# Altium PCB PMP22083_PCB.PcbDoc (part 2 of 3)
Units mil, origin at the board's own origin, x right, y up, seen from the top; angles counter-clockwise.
Board outline 6200 x 4200 mil, 2 copper layers (Top Layer, Bottom Layer), stack 62 mil thick; 186 components, 87 nets, 426 pads, 96 vias.
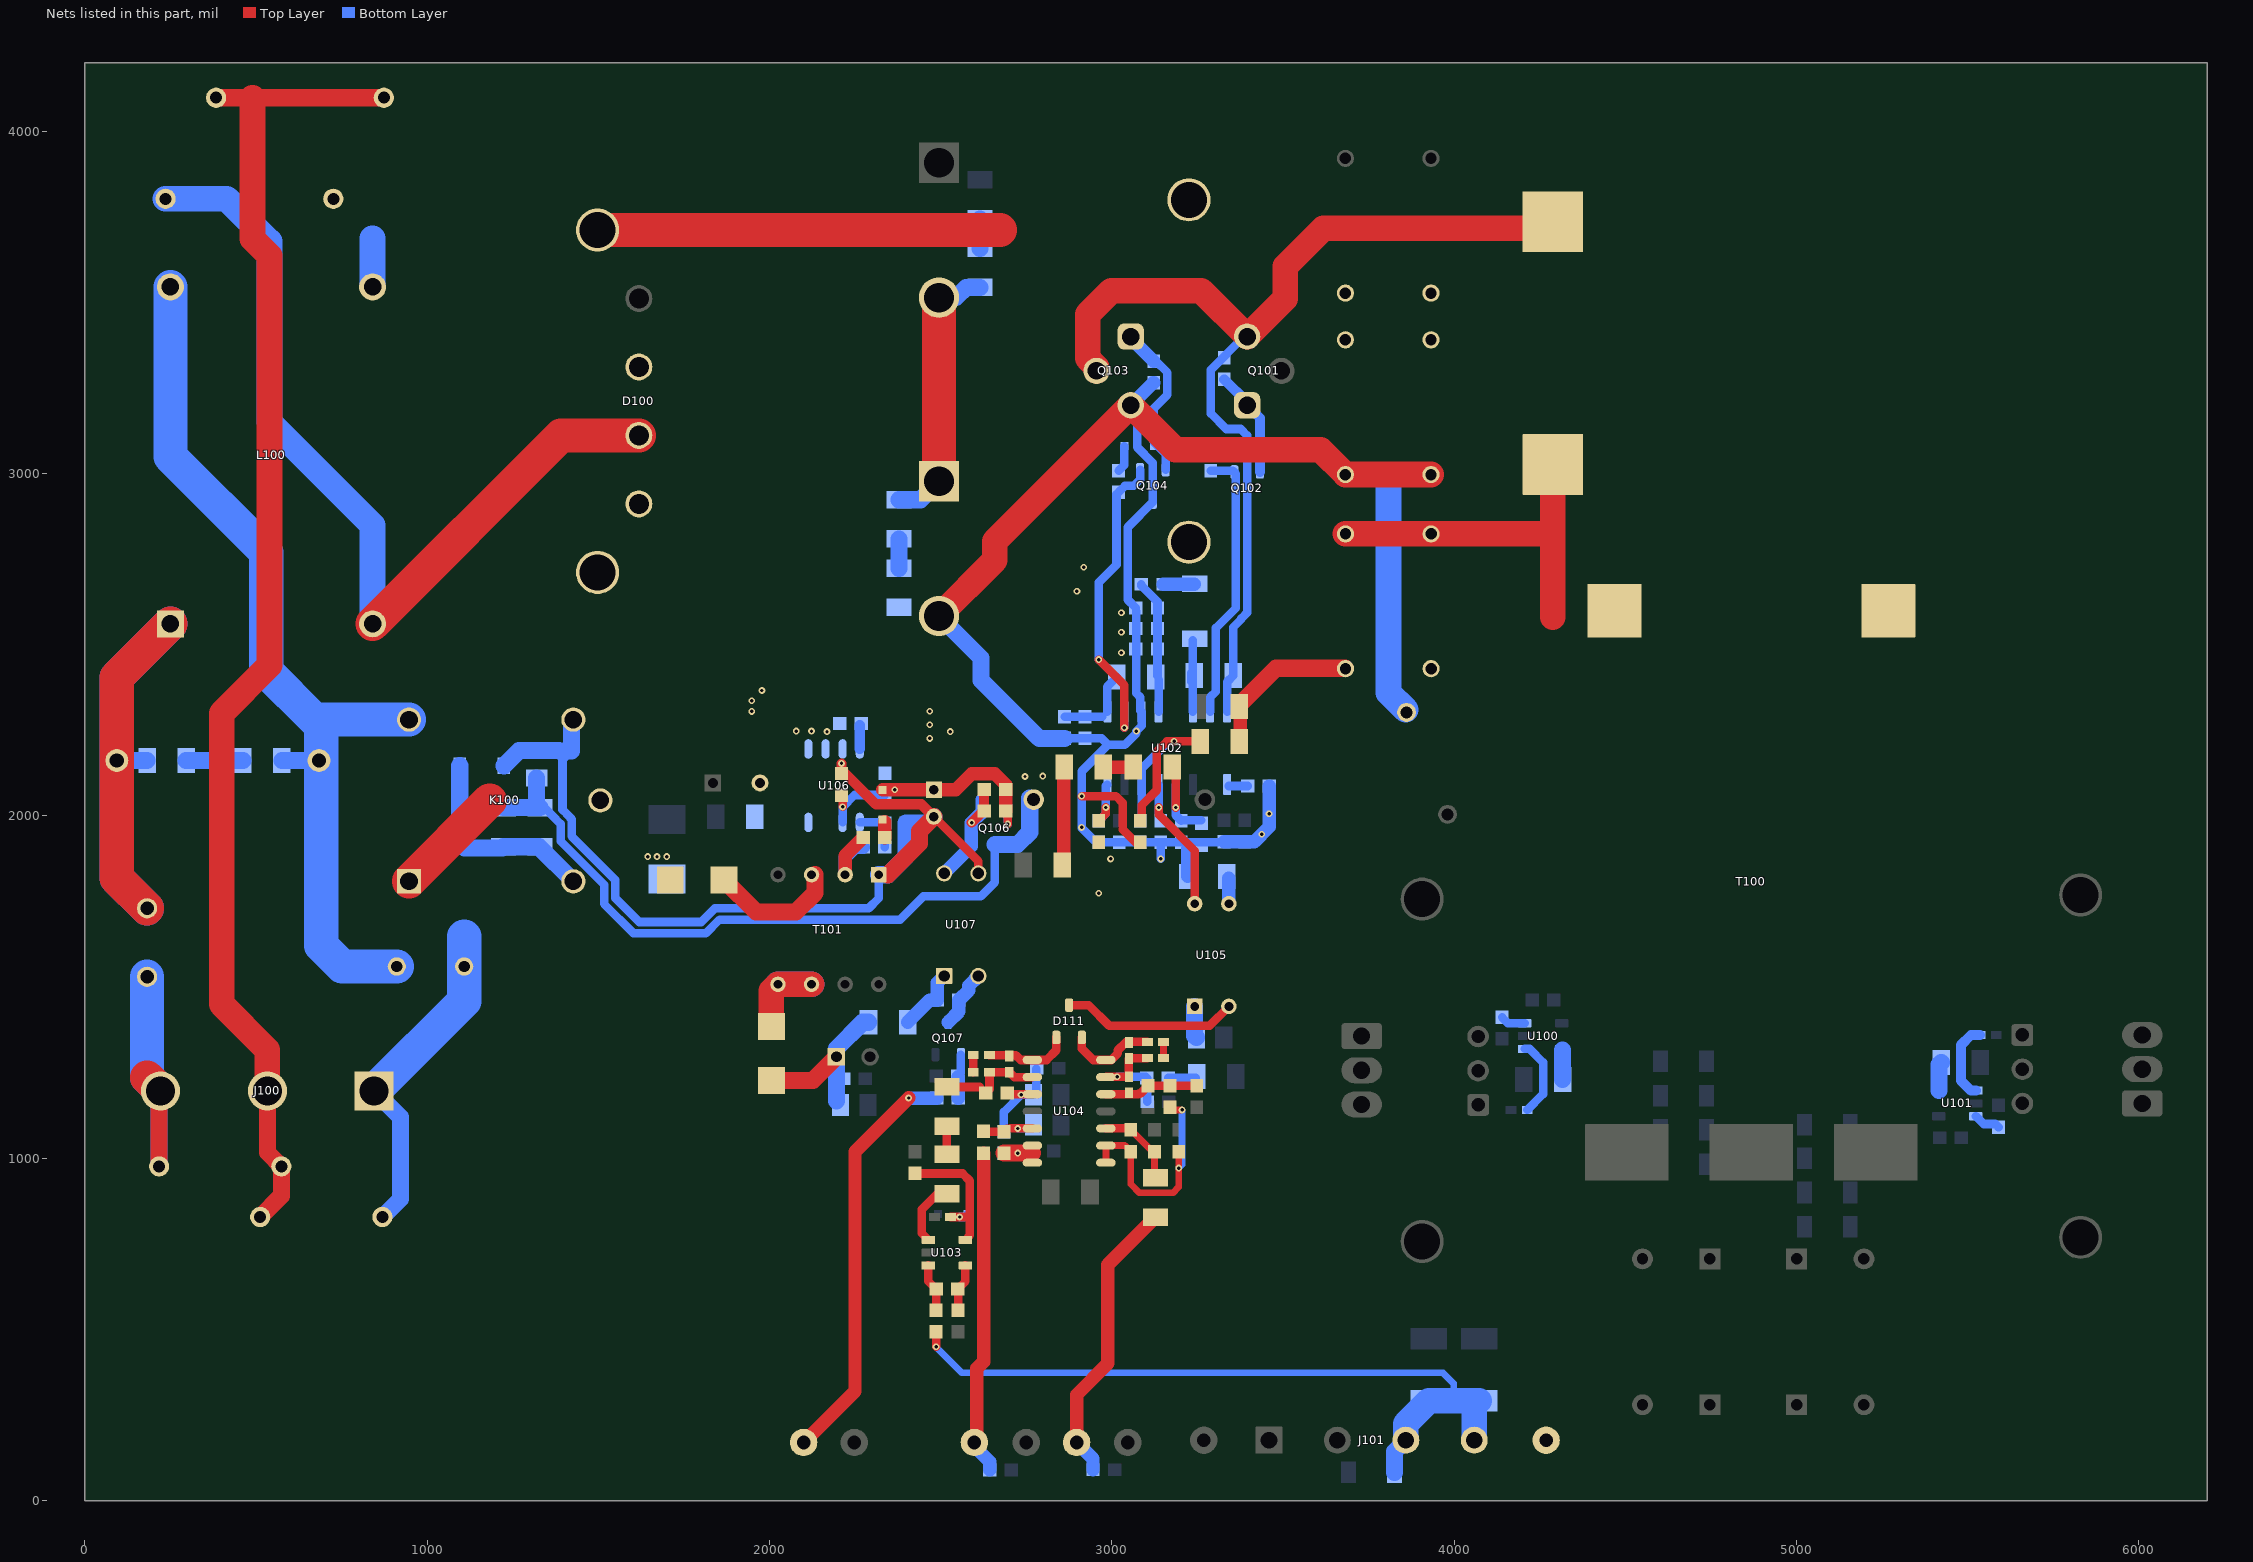
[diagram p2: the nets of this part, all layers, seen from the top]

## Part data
C100 C108: library part CMP-0010098-2, "CAP, AL, 560 uF, 200 V, +/- 20%, TH", Manufacturer=Nichicon, PartNumber=LGR2D561MELZ45, Tolerance_%=20%, Value1=Unknown, Value2=200V, ValueDisplayed=560uF
C101 C103: "CAP, CERM, 2.2 £gF, 16 V,+/- 20%, X5R, 0603", Cap_Case=0603, Manufacturer="Wurth Elektronik", Supplier Part Number 1=732-7915-1-ND, TempCo=X5R, Tolerance_%=20, Value2=16V, ValueDisplayed=2.2£gF
C102 C104: "CAP, CERM, 0.1 £gF, 50 V,+/- 10%, X7R, 0603", Cap_Case=0603, Manufacturer="Wurth Elektronik", TempCo=X7R, Tolerance_%=10, Value2=50V, ValueDisplayed=0.1£gF
C105 C106 C110 C111: "CAP, CERM, 470pF, 300V, +/-10%, VY2, 5x7.5 mm", Cap_Case="Disk, 5x7.5 mm", Manufacturer=Vishay-Bccomponents, Supplier Part Number 1=BC2352-ND, TempCo=VY2, Tolerance_%=10, Value1=Unknown, Value2=300V, ValueDisplayed=470pF
C107: "CAP, Film, 0.33uF, 275V, +/-20%, TH", Cap_Case=Radial,17.5x17.5x9.5mm, Manufacturer=Panasonic, Supplier Part Number 1=P10733-ND, Tolerance_%=20, Value1=Unknown, Value2=275V, ValueDisplayed=0.33£gF
C109: "CAP, CERM, 2200 pF, 300 V, +/- 20%, Y5U, AEC-Q200 Grade 1, D9.5xT5mm", Cap_Case=9.5x5mm, Manufacturer=Vishay-Bccomponents, Supplier Part Number 1=BC2914-ND, TempCo=Y5U, Tolerance_%=20, Value1=Unknown, Value2=300V, ValueDisplayed=2200pF
C112 C113 C114 C115 C116 C117: library part CMP-0074802-2, "CAP FILM 10000PF 5% 1KVDC RADIAL", Cap_Case=13x6x12mm, Manufacturer=TDK, Tolerance_%=5%, Value2=1000V, ValueDisplayed=0.01£gF
C118: "CAP, CERM, 22 pF, 1000 V,+/- 5%, C0G/NP0, 1206", Cap_Case=1206, Manufacturer=Vishay-Vitramon, Supplier Part Number 1=720-1013-1-ND, TempCo=C0G/NP0, Tolerance_%=5, Value2=1kV, ValueDisplayed=22pF
C119: "CAP, CERM, 150 pF, 630 V, +/- 5%, C0G/NP0, 1206", Cap_Case=1206, Manufacturer=MuRata, Supplier Part Number 1=490-5274-1-ND, TempCo=C0G/NP0, Tolerance_%=5, Value1=Unknown, Value2=630V, ValueDisplayed=150pF
C120 C121 C122 C123 C128 C165 C166 C167 C168: "CAP, CERM, 4.7 £gF, 50 V,+/- 10%, X7R, 1206", Cap_Case=1206, Manufacturer="Taiyo Yuden", Supplier Part Number 1=587-2994-2-ND, TempCo=X7R, Tolerance_%=10, Value2=50V, ValueDisplayed=4.7£gF
C124 C125 C126 C127: library part EEU-FR1V681, "CAP ALUM POLY 470UF 20% 25V T/H", Manufacturer=Panasonic, Tolerance_%=20, Value2=25V, ValueDisplayed=470£gF
C129: "CAP, CERM, 1uF, 16V, +/-10%, X5R, 0805", Cap_Case=0805, Manufacturer=AVX, Supplier Part Number 1=478-1411-1-ND, TempCo=X5R, Tolerance_%=10, Value1="0.012 ohm", Value2=16V, ValueDisplayed=1£gF
C130: "CAP, CERM, 2.2 £gF, 16 V, +/- 10%, X7R, 1206", Cap_Case=1206, Manufacturer=Kemet, Supplier Part Number 1=80-C1206C225K4R, TempCo=X7R, Tolerance_%=10, Value1="0.009 ohm", Value2=16V, ValueDisplayed=2.2£gF
C131: "CAP, CERM, 47 pF, 50 V, +/- 5%, C0G/NP0, 0603", Cap_Case=0603, Manufacturer=Kemet, Supplier Part Number 1=399-1056-1-ND, TempCo=C0G/NP0, Tolerance_%=5, Value1=Unknown, Value2=50V, ValueDisplayed=47pF
C132: "CAP, CERM, 0.1 £gF, 25 V, +/- 10%, X5R, 0402", Cap_Case=0402, Manufacturer=MuRata, Supplier Part Number 1=81-GRM155R61E104KA7D, TempCo=X5R, Tolerance_%=10, Value1=Unknown, Value2=25V, ValueDisplayed=0.1£gF
C133: "CAP, CERM, 0.1 £gF, 50 V, +/- 10%, X7R, 1206", Cap_Case=1206, Manufacturer=Kemet, Supplier Part Number 1=399-1249-1-ND, TempCo=X7R, Tolerance_%=10, Value1="0.059 ohm", Value2=50V, ValueDisplayed=0.1£gF
C134 C135 C139 C140 C141: "CAP, CERM, 4.7 £gF, 16 V, +/- 10%, X5R, 0603", Cap_Case=0603, Manufacturer=MuRata, Supplier Part Number 1=490-10481-1-ND, TempCo=X5R, Tolerance_%=10, Value1=Unknown, Value2=16V, ValueDisplayed=4.7£gF
C136 C155: "CAP, CERM, 0.01 £gF, 50 V, +/- 10%, X7R, 0402", Cap_Case=0402, Manufacturer=MuRata, Supplier Part Number 1=490-4516-1-ND, TempCo=X7R, Tolerance_%=10, Value1=Unknown, Value2=50V, ValueDisplayed=0.01£gF
C137: "CAP, CERM, 0.033 £gF, 16 V,+/- 10%, X5R, 0402", Cap_Case=0402, Manufacturer=MuRata, Supplier Part Number 1=490-5416-1-ND, TempCo=X5R, Tolerance_%=10, Value2=16V, ValueDisplayed=0.033£gF
C138: "CAP, CERM, 22 pF, 50 V,+/- 5%, C0G/NP0, 0603", Cap_Case=0603, Manufacturer=AVX, Supplier Part Number 1=478-1167-1-ND, TempCo=C0G/NP0, Tolerance_%=5, Value1="0.259 ohm", Value2=50V, ValueDisplayed=22pF
C142: "CAP, CERM, 0.47 £gF, 10 V,+80/-20%, Y5V, 0603", Cap_Case=0603, Manufacturer=Kemet, Supplier Part Number 1=399-3218-1-ND, TempCo=Y5V, Tolerance_%=80, Value2=10V, ValueDisplayed=0.47£gF
C143: "CAP, CERM, 2700 pF, 25 V,+/- 10%, X7R, 0603", Cap_Case=0603, Manufacturer=MuRata, Supplier Part Number 1=GRM188R71E272KA01D-ND, TempCo=X7R, Tolerance_%=10, Value2=25V, ValueDisplayed=2700pF
C144: "CAP, CERM, 47 pF, 50 V, +/- 1%, C0G/NP0, 0603", Cap_Case=0603, Manufacturer=MuRata, Supplier Part Number 1=490-9687-1-ND, TempCo=C0G/NP0, Tolerance_%=1, Value1=Unknown, Value2=50V, ValueDisplayed=47pF
C145: "CAP, CERM, 220 pF, 50 V, +/- 10%, X7R, 0603", Cap_Case=0603, Manufacturer=MuRata, Supplier Part Number 1=490-1483-1-ND, TempCo=X7R, Tolerance_%=10, Value1=Unknown, Value2=50V, ValueDisplayed=220pF
C146: "CAP, CERM, 2.2 pF, 50 V, +/- 11%, C0G/NP0, 0603", Cap_Case=0603, Manufacturer=AVX, Supplier Part Number 1=478-1155-1-ND, TempCo=C0G/NP0, Tolerance_%=11, Value1="1.033 ohm", Value2=50V, ValueDisplayed=2.2pF
C147 C148 C160: "CAP, CERM, 47 pF, 50 V,+/- 5%, C0G/NP0, 0603", Cap_Case=0603, Manufacturer=MuRata, Supplier Part Number 1=490-1419-1-ND, TempCo=C0G/NP0, Tolerance_%=5, Value2=50V, ValueDisplayed=47pF
C149 C150: "CAP, CERM, 0.1 £gF, 25 V,+/- 5%, X7R, 0805", Cap_Case=0805, Manufacturer=AVX, Supplier Part Number 1=478-7946-1-ND, TempCo=X7R, Tolerance_%=5, Value2=25V, ValueDisplayed=0.1£gF
C151: "CAP, AL, 2.2 £gF, 450 V, +/- 20%, 150.71 ohm, TH", Cap_Case=8x11.5mm, Manufacturer="Illinois Capacitor", Supplier Part Number 1=225CKE450MJM-ND, Tolerance_%=20, Value1="150.71 ohm", Value2=450V, ValueDisplayed=2.2£gF
C152: "CAP, CERM, 0.01 £gF, 250 V,+/- 10%, X7R, 1206", Cap_Case=1206, Manufacturer=Kemet, Supplier Part Number 1=399-4671-1-ND, TempCo=X7R, Tolerance_%=10, Value2=250V, ValueDisplayed=0.01£gF
C153: "CAP, AL, 100 £gF, 25 V, +/- 20%, TH", Cap_Case=6.3x11.2mm, Manufacturer=Panasonic, Supplier Part Number 1=P5540-ND, Tolerance_%=20, Value2=25V, ValueDisplayed=100£gF
C154: "CAP, CERM, 0.1uF, 25V, +/-10%, X7R, 0805", Cap_Case=0805, Manufacturer=AVX, Supplier Part Number 1=478-3755-1-ND, TempCo=X7R, Tolerance_%=10, Value1="0.28 ohm", Value2=25V, ValueDisplayed=0.1u
C156: "CAP, CERM, 0.022 £gF, 50 V,+/- 10%, C0G/NP0, 0402", Cap_Case=0402, Manufacturer=MuRata, Supplier Part Number 1=490-4763-1-ND, TempCo=C0G/NP0, Tolerance_%=10, Value2=50V, ValueDisplayed=0.022£gF
C157: "CAP, CERM, 0.01 £gF, 16 V,+/- 10%, X7R, 0603", Cap_Case=0603, Manufacturer="Wurth Elektronik", Supplier Part Number 1=732-7959-1-ND, TempCo=X7R, Tolerance_%=10, Value2=16V, ValueDisplayed=0.01£gF
C158: "CAP, CERM, 0.1uF, 50V, +/-10%, X7R, 0603", Cap_Case=0603, Manufacturer=AVX, Supplier Part Number 1=478-5052-1-ND, TempCo=X7R, Tolerance_%=10, Value1=Unknown, Value2=50V, ValueDisplayed=0.1u
C159: "CAP, CERM, 47 pF, 50 V,+/- 5%, C0G/NP0, 0402", Cap_Case=0402, Manufacturer=MuRata, Supplier Part Number 1=81-GRM1555C1H470JA1D, TempCo=C0G/NP0, Tolerance_%=5, Value2=50V, ValueDisplayed=47pF
C161 C162: "CAP, CERM, 0.1 £gF, 50 V,+/- 10%, X7R, 0603", Cap_Case=0603, Manufacturer=AVX, Supplier Part Number 1=478-5052-1-ND, TempCo=X7R, Tolerance_%=10, Value2=50V, ValueDisplayed=0.1£gF
C163: library part 25ML22MEFC5X5, "CAP, AL, 18uF, 35V, +/-20%, TH", Cap_Case=5x5, Manufacturer=Rubycon, Tolerance_%=20, Value1=Unknown, Value2=35V, ValueDisplayed=18u
C164: "CAP, CERM, 2.2 £gF, 35 V, +/- 10%, X5R, 0603", Cap_Case=0603, Manufacturer=MuRata, Supplier Part Number 1=490-7204-6-ND, TempCo=X5R, Tolerance_%=10, Value1=Unknown, Value2=35V, ValueDisplayed=2.2£gF
CCset CVset PSON Vout: "Test Point, Miniature, Red, TH", Color=Red, Manufacturer=Keystone, Supplier Part Number 1=36-5000-ND
D100: "Diode, Switching-Bridge, 420V, 8A, TH", Manufacturer="Micro Commercial Components", Supplier Part Number 1=GBU8J-BPMS-ND, Value1=8A, Value2=1V
D101 D105: "Diode, Switching, 100 V, 0.2 A, SOD-323", Manufacturer="Micro Commercial Components", Supplier Part Number 1=MMDL914-TPMSCT-ND, Value1=0.2A, Value2=1V
D102 D106: library part STPS41H100CTY, "DIODE ARRAY SCHOTTKY 60V TO220AB", Manufacturer=STMicroelectronics, Value1=20A
D103: "Diode, Zener, 12 V, 500 mW, SOD-123", Manufacturer="ON Semiconductor", Power_W=0.5, Supplier Part Number 1=MMSZ4699T1GOSCT-ND, Value1=0.5W
D104: "Diode, Ultrafast, 100 V, 0.25 A, SOD-323", Manufacturer="NXP Semiconductor", Supplier Part Number 1=568-5003-1-ND, Value1=0.25A, Value2=1.4V
D107: "Diode, Ultrafast, 600 V, 1 A, AEC-Q101, SMAF", Manufacturer="Fairchild Semiconductor", Supplier Part Number 1=ES1JAFCT-ND, Value1=1A, Value2=1.7V
D108: "Diode, Zener, 5.1 V, 200 mW, SOD-323", Manufacturer="Diodes Inc.", Power_W=0.2, Supplier Part Number 1=MMSZ5231BS-FDICT-ND, Value1=0.2W
D109: "Diode, Schottky, 100 V, 1 A, SMA", Manufacturer="Micro Commercial Components", Supplier Part Number 1=SS110-TPCT-ND, Value1=1A, Value2=0.85V
D110: library part SMBJ120A-13-F, "Diode, TVS, Uni, 160V, 3W, SMB", Manufacturer="Diodes Inc.", Power_W=5, Supplier Part Number 1=1SMB5954BT3GOSCT-ND, Value1=3W
D111: "Diode, Schottky, 30 V, 0.2 A, SOT-23", Manufacturer="Diodes Inc.", Supplier Part Number 1=BAT54A-FDICT-ND, Value1=0.2A, Value2=0.65V
D112: "Diode, Ultrafast, 1000V, 1A, SMA", Manufacturer="Diodes Inc.", Supplier Part Number 1=US1M-FDICT-ND, Value1=1A, Value2=1000V
D113: library part BAS316,115, "DIODE SWITCH 200V 200MA SOD323", Supplier Part Number 1=BAS20HT1GOSTR-ND, Value1=0.25A, Value2=100V
F100: "Fuse, 6.3 A, 250VAC/VDC, TH", Irating_A=6.3A, Manufacturer=Littelfuse, Supplier Part Number 1=WK6336CT-ND
H100: "Heatsink, TO-220 Vertical", Manufacturer=Aavid, Supplier Part Number 1=532602B02500G-ND
H101 H102 H103: library part 531202B02500G, "HEATSINK TO-220 W/PINS 2\" TALL", Manufacturer=Aavid
J100: library part CMP-0054856-1, "Header, 312mil, 3x1, Tin, TH", Manufacturer="TE Connectivity", Supplier Part Number 1=A30522-ND
J101: "Terminal Block, 5.08 mm, 4x1, Brass, TH", Color=Blue, Current_A=15, Manufacturer="On-Shore Technology", Supplier Part Number 1=ED2227-ND, Voltage_V=300
J102: library part CMP-0055441-1, "Jumper Wire, 500mil spacing, Green, pkg of 200", Manufacturer=3M, Supplier Part Number 1=923345-05-ND
K100: library part 875B-1CC-F-S-12VDC, "Relay, SPDT ( 1 Form C), 16A, 12 VDC, TH", Coil Current="30 mA", Coil Power="360 mW", Coil Resistance="400 ohms", Coil Voltage="12 VDC", Contact Rating=16A, Manufacturer=Omron, Turn Off Voltage (Min)="0.6 VDC", Turn On Voltage (Max)="9 VDC"
L100: library part 744825510, "Coupled inductor, 5 mH, 6A, TH", Manufacturer="Wurth Elektronik", ValueDisplayed=5mH
L101: library part CMP-0086704-1, "30uH & 8A INDUCTOR", Manufacturer="Payton Planar"
LOGO100: library part CMP-0074835-1, "IEC 61010-1 High Voltage Warning"
LOGO101: library part CMP-0074837-1, "IEC 61010-1 Hot Surface Warning"
Logo102: library part Pb-Free
Logo103: library part CMP-0074769-1
Logo104: library part CMP-0074847-1, "FCC_disclaimer"
Q100 Q105: "MOSFET, N-CH, 80 V, 150 A, KCS0003B (TO-220-3)", Alternate Manufacturer=None, Manufacturer="Texas Instruments", Supplier Part Number 1=296-37287-5-ND, Value1="? ohm", Value2="76 nC"
Q101 Q103: library part IPA65R190CFD, "N-Channel 600V 25A (Tc) 125W (Tc) Through Hole PG-TO220-3", Alternate Manufacturer=None, Manufacturer="Infineon Technologies", Value1="? ohm", Value2="68 nC"
Q102 Q104: library part "FMMT718TA, Diodes Inc.", "Transistor, PNP, 20 V, 1.5 A, SOT-23", Manufacturer="Diodes Inc.", Supplier Part Number 1=FMMT718CT-ND, Value1="1.5 A", Value2=6
Q106: library part SI2309CDS-T1-E3, "MOSFET, P-CH, -60 V, -1.6 A, SOT-23", Alternate Manufacturer=None, Manufacturer=Vishay-Siliconix, Supplier Part Number 1=SI2309CDS-T1-E3CT-ND, Value1="0.45 ohm", Value2="2.7 nC"
Q107: "MOSFET, N-CH, 60 V, 0.17 A, SOT-23", Alternate Manufacturer=None, Manufacturer="Diodes Inc.", Supplier Part Number 1=2N7002-FDICT-ND, Value1="7.5 ohm", Value2="223 nC"
R100 R101: "RES, 4.99 k, 1%, 0.25 W, 1206", Manufacturer=Vishay-Dale, Power_W=0.25, Supplier Part Number 1=541-4.99KFCT-ND, TempCo="100 ppm/C", Tolerance_%=1, Value1=1%, Value2=0.25W, Value_Code=4k99, ValueDisplayed=4.99k
R102 R105 R107 R109: "RES, 1.00 M, 1%, 0.25 W, 1206", Manufacturer=Vishay-Dale, Power_W=0.25, Supplier Part Number 1=541-1.00MFCT-ND, TempCo="100 ppm/C", Tolerance_%=1, Value1=1%, Value2=0.25W, Value_Code=1M00, ValueDisplayed=1.00M
R103 R104: "RES, 0, 5%, 0.063 W, 0402", Manufacturer=Vishay-Dale, Power_W=0.063, Supplier Part Number 1=541-0.0JCT-ND, TempCo="200 ppm/C", Tolerance_%=5, Value1=5%, Value2=0.063W, Value_Code=0000, ValueDisplayed=0
R106 R108: "RES, 499 k, 1%, 0.25 W, 1206", Manufacturer=Vishay-Dale, Power_W=0.25, Supplier Part Number 1=541-499KFCT-ND, TempCo="100 ppm/C", Tolerance_%=1, Value1=1%, Value2=0.25W, Value_Code=499k
R110 R114: "RES, 10.0, 1%, 0.1 W, 0603", Manufacturer=Vishay-Dale, Power_W=0.1, Supplier Part Number 1=541-10.0HCT-ND, TempCo="100 ppm/C", Tolerance_%=1, Value1=1%, Value2=0.1W, Value_Code=10R0, ValueDisplayed=10.0
R111 R115: "RES, 20.0 k, 1%, 0.1 W, 0603", Manufacturer=Vishay-Dale, Power_W=0.1, Supplier Part Number 1=541-20.0KHCT-ND, TempCo="100 ppm/C", Tolerance_%=1, Value1=1%, Value2=0.1W, Value_Code=20k0, ValueDisplayed=20.0k
R112 R113: "RES, 150, 5%, 0.25 W, 1206", Manufacturer=Vishay-Dale, Power_W=0.25, Supplier Part Number 1=541-150ECT-ND, TempCo="200 ppm/C", Tolerance_%=5, Value1=5%, Value2=0.25W, Value_Code=150R, ValueDisplayed=150
R116 R117: "RES, 0.002, 1%, 1 W, 2010", Manufacturer=Rohm, Power_W=1, Supplier Part Number 1=RHM.002ASCT-ND, TempCo="100 ppm/C", Value1=1%, Value2=1W, Value_Code=2L000, ValueDisplayed=0.002
R118: "RES, 2.2, 5%, 0.1 W, 0603", Manufacturer=Vishay-Dale, Power_W=0.1, Supplier Part Number 1=541-2.2GCT-ND, TempCo="200 ppm/C", Tolerance_%=5, Value1=5%, Value2=0.1W, Value_Code=2R20, ValueDisplayed=2.2
R119 R120: "RES, 4.75, 1%, 0.1 W, 0603", Manufacturer="Yageo America", Power_W=0.1, Supplier Part Number 1=311-4.75HRCT-ND, TempCo="200 ppm/C", Tolerance_%=1, Value1=1%, Value2=0.1W, Value_Code=4R75, ValueDisplayed=4.75
R121: "RES, 10.0 k, 1%, 0.1 W, 0603", Manufacturer=Vishay-Dale, Power_W=0.1, Supplier Part Number 1=541-10.0KHCT-ND, TempCo="100 ppm/C", Tolerance_%=1, Value1=1%, Value2=0.1W, Value_Code=10k0, ValueDisplayed=10.0k
R122: "RES, 0, 5%, 0.1 W, 0603", Manufacturer=Vishay-Dale, Power_W=0.1, Supplier Part Number 1=541-0.0GCT-ND, TempCo="200 ppm/C", Tolerance_%=5, Value1=5%, Value2=0.1W, Value_Code=0000, ValueDisplayed=0
R123 R124 R126: "RES, 4.99 M, 1%, 0.25 W, 1206", Manufacturer=Vishay-Dale, Power_W=0.25, Supplier Part Number 1=541-4.99MFCT-ND, TempCo="100 ppm/C", Tolerance_%=1, Value1=1%, Value2=0.25W, Value_Code=4M99, ValueDisplayed=4.99M
R125: "RES, 866 k, 1%, 0.25 W, 1206", Manufacturer=Vishay-Dale, Power_W=0.25, Supplier Part Number 1=541-866KFCT-ND, TempCo="100 ppm/C", Tolerance_%=1, Value1=1%, Value2=0.25W, Value_Code=866k
R127: "RES, 1.00 k, 1%, 0.25 W, 1206", Manufacturer=Vishay-Dale, Power_W=0.25, Supplier Part Number 1=541-1.00KFCT-ND, TempCo="100 ppm/C", Tolerance_%=1, Value1=1%, Value2=0.25W, Value_Code=1k00, ValueDisplayed=1.00k
R128: "RES, 20.5, 1%, 0.25 W, 1206", Manufacturer=Vishay-Dale, Power_W=0.25, Supplier Part Number 1=541-20.5FCT-ND, TempCo="100 ppm/C", Tolerance_%=1, Value1=1%, Value2=0.25W, Value_Code=20R5, ValueDisplayed=20.5
R129: "RES, 40.2, 1%, 0.1 W, 0603", Manufacturer=Vishay-Dale, Power_W=0.1, Supplier Part Number 1=541-40.2HCT-ND, TempCo="100 ppm/C", Tolerance_%=1, Value1=1%, Value2=0.1W, Value_Code=40R2, ValueDisplayed=40.2
R130: "RES, 1.00 k, 1%, 0.063 W, 0402", Manufacturer=Vishay-Dale, Power_W=0.063, Supplier Part Number 1=541-1.00KLCT-ND, TempCo="100 ppm/C", Tolerance_%=1, Value1=1%, Value2=0.063W, Value_Code=1k00, ValueDisplayed=1.00k
R131: "RES, 750 k, 1%, 0.1 W, 0603", Manufacturer=Vishay-Dale, Power_W=0.1, Supplier Part Number 1=541-750KHCT-ND, TempCo="100 ppm/C", Tolerance_%=1, Value1=1%, Value2=0.1W, Value_Code=750k
R132: "RES, 249 k, 1%, 0.1 W, 0603", Manufacturer=Vishay-Dale, Power_W=0.1, Supplier Part Number 1=541-249KHCT-ND, TempCo="100 ppm/C", Tolerance_%=1, Value1=1%, Value2=0.1W, Value_Code=249k
R133: "RES, 6.65 k, 1%, 0.1 W, 0603", Manufacturer=Vishay-Dale, Power_W=0.1, Supplier Part Number 1=541-6.65KHCT-ND, TempCo="100 ppm/C", Tolerance_%=1, Value1=1%, Value2=0.1W, Value_Code=6k65, ValueDisplayed=6.65k
R134 R135: "RES, 39.0 k, 1%, 0.1 W, 0603", Manufacturer="Yageo America", Power_W=0.1, Supplier Part Number 1=311-39.0KHRCT-ND, TempCo="200 ppm/C", Tolerance_%=1, Value1=1%, Value2=0.1W, Value_Code=39k0, ValueDisplayed=39.0k
R136: "RES, 10.0 k, 1%, 0.125 W, 0805", Manufacturer=Vishay-Dale, Power_W=0.125, Supplier Part Number 1=541-10.0KCCT-ND, TempCo="100 ppm/C", Tolerance_%=1, Value1=1%, Value2=0.125W, Value_Code=10k0, ValueDisplayed=10.0k
R137: "RES, 5.36 k, 1%, 0.1 W, 0603", Manufacturer=Vishay-Dale, Power_W=0.1, Supplier Part Number 1=541-5.36KHCT-ND, TempCo="100 ppm/C", Tolerance_%=1, Value1=1%, Value2=0.1W, Value_Code=5k36, ValueDisplayed=5.36k
R138 R157: "RES, 15.0 k, 1%, 0.1 W, 0603", Manufacturer=Vishay-Dale, Power_W=0.1, Supplier Part Number 1=541-15.0KHCT-ND, TempCo="100 ppm/C", Tolerance_%=1, Value1=1%, Value2=0.1W, Value_Code=15k0, ValueDisplayed=15.0k
R139 R158: "RES, 1.00 M, 1%, 0.1 W, 0603", Manufacturer=Vishay-Dale, Power_W=0.1, Supplier Part Number 1=541-1.00MHCT-ND, TempCo="100 ppm/C", Tolerance_%=1, Value1=1%, Value2=0.1W, Value_Code=1M00, ValueDisplayed=1.00M
R140: "RES, 2.0k ohm, 5%, 0.1W, 0603", Manufacturer=Vishay-Dale, Power_W=0.1, Supplier Part Number 1=71-CRCW06032K00JNEA, TempCo="200 ppm/C", Tolerance_%=5, Value1=5%, Value2=0.1W, Value_Code=2k00
R141: "RES, 0, 5%, 0.25 W, 1206", Manufacturer=Vishay-Dale, Power_W=0.25, Supplier Part Number 1=541-0.0ECT-ND, TempCo="200 ppm/C", Tolerance_%=5, Value1=5%, Value2=0.25W, Value_Code=0000, ValueDisplayed=0
R142: "RES, 49.9, 1%, 0.25 W, 1206", Manufacturer="Yageo America", Power_W=0.25, Supplier Part Number 1=311-49.9FRCT-ND, TempCo="100 ppm/C", Tolerance_%=1, Value1=1%, Value2=0.25W, Value_Code=49R9, ValueDisplayed=49.9
R143: "RES, 20.0 k, 1%, 0.063 W, 0402", Manufacturer=Vishay-Dale, Power_W=0.063, Supplier Part Number 1=541-20.0KLCT-ND, TempCo="100 ppm/C", Tolerance_%=1, Value1=1%, Value2=0.063W, Value_Code=20k0, ValueDisplayed=20.0k
R144: "RES, 1.00 ohm, 1%, 0.1W, 0603", Manufacturer="Yageo America", Power_W=0.1, Supplier Part Number 1=311-1.00HRCT-ND, TempCo="200 ppm/C", Tolerance_%=1, Value1=1%, Value2=0.1W, Value_Code=1R00
R145 R151 R155: "RES, 18.7 k, 1%, 0.1 W, 0603", Manufacturer=Vishay-Dale, Power_W=0.1, Supplier Part Number 1=541-18.7KHCT-ND, TempCo="100 ppm/C", Tolerance_%=1, Value1=1%, Value2=0.1W, Value_Code=18k7, ValueDisplayed=18.7k
R146: "RES, 60.4k ohm, 1%, 0.1W, 0603", Manufacturer=Vishay-Dale, Power_W=0.1, Supplier Part Number 1=541-60.4KHCT-ND, TempCo="100 ppm/C", Tolerance_%=1, Value1=1%, Value2=0.1W, Value_Code=60k4
R147: "RES, 20.0 k, 1%, 0.25 W, 1206", Manufacturer=Vishay-Dale, Power_W=0.25, Supplier Part Number 1=541-20.0KFCT-ND, TempCo="100 ppm/C", Tolerance_%=1, Value1=1%, Value2=0.25W, Value_Code=20k0, ValueDisplayed=20.0k
R148 R159: "RES, 100 k, 1%, 0.1 W, 0603", Manufacturer=Vishay-Dale, Power_W=0.1, Supplier Part Number 1=541-100KHCT-ND, TempCo="100 ppm/C", Tolerance_%=1, Value1=1%, Value2=0.1W, Value_Code=100k
R149: "RES, 2.43k ohm, 1%, 0.1W, 0603", Manufacturer=Vishay-Dale, Power_W=0.1, Supplier Part Number 1=541-2.43KHCT-ND, TempCo="100 ppm/C", Tolerance_%=1, Value1=1%, Value2=0.1W, Value_Code=2k43
R150: "RES, 47.5 k, 1%, 0.1 W, AEC-Q200 Grade 0, 0603", Manufacturer=Panasonic, Power_W=0.1, Supplier Part Number 1=P47.5KHCT-ND, TempCo="100 ppm/C", Tolerance_%=1, Value1=1%, Value2=0.1W, Value_Code=47k5, ValueDisplayed=47.5k
R152: "RES, 39.0 k, 1%, 0.25 W, AEC-Q200 Grade 0, 1206", Manufacturer=Panasonic, Power_W=0.25, Supplier Part Number 1=P39.0KFCT-ND, TempCo="100 ppm/C", Tolerance_%=1, Value1=1%, Value2=0.25W, Value_Code=39k0, ValueDisplayed=39.0k
R153: "RES, 16.5k ohm, 1%, 0.1W, 0603", Manufacturer=Vishay-Dale, Power_W=0.1, Supplier Part Number 1=541-16.5KHCT-ND, TempCo="100 ppm/C", Tolerance_%=1, Value1=1%, Value2=0.1W, Value_Code=16k5
R154: "RES, 1.0 k, 5%, 0.1 W, 0603", Manufacturer=Vishay-Dale, Power_W=0.1, Supplier Part Number 1=541-1.0KGCT-ND, TempCo="200 ppm/C", Tolerance_%=5, Value1=5%, Value2=0.1W, Value_Code=1k00, ValueDisplayed=1.0k
R156: "RES, 2.49 k, 1%, 0.1 W, 0603", Manufacturer="Yageo America", Power_W=0.1, Supplier Part Number 1=311-2.49KHRCT-ND, TempCo="200 ppm/C", Tolerance_%=1, Value1=1%, Value2=0.1W, Value_Code=2k49, ValueDisplayed=2.49k
RT100: "Thermistor NTC, 50 ohm, 25%, D12.5xH16.5mm", Manufacturer=TDK, Supplier Part Number 1=495-3880-ND, Tolerance_%=25
SGND SGND SGND: "Test Point, Miniature, Black, TH", Manufacturer=Keystone, Supplier Part Number 1=5001K-ND
SGND: "Test Point, Miniature, Black, TH", Color=Black, Manufacturer=Keystone, Supplier Part Number 1=36-5001-ND
T100: library part CMP-0089702-1, "264W SMPS TRANSFORMER", Frequency_Fixed=200-400kHz, Manufacturer="Payton Planar", Operating Temperature Range=to, Part Number=61201, Voltage_Isolation_Vrms=1500Vrms
T101: library part CMP-0088854-1, "800uH DCM Flyback, 15V", Manufacturer=Renco, Operating Temperature Range=to, Voltage_Isolation_Vrms=1.5kV
U100 U101: library part CMP-0013050-3, "UCC24612-2DBV, DBV0005A (SOT-23-5)", Alternate Manufacturer="Texas Instruments", Alternate PartNumber=UCC24612-2DBVT, PartNumber=UCC24612-2DBVR
U102: library part UCC25630DDB, "Enhanced LLC Resonant Controller with Driver, DDB0014A", Alternate Manufacturer="Texas Instruments"
U103: "Low- and High-Side Measurement, Multichannel, Voltage Output, Current-Sense Amplifier, DBV0005A (SOT-5)", Alternate Manufacturer="Texas Instruments"
U104: library part CMP-0068270-1, "Low Power Quad Operational Amplifier, 14-pin Narrow SOIC", Manufacturer="Texas Instruments", Package Reference=D0014A, PackageTopMarking=NSUZXYTTE#*LM324M, PowerWise=N
U105: library part CMP-0006187-2, "OPTOISOLATOR 5.3KV TRANS 4-DIP", Manufacturer=Vishay-Semiconductor, PartNumber=VO618A-3, Voltage_Isolation_Vrms=5.3kV
U106: library part CMP-0067241-2, "700V Flyback Switcher with Constant-Voltage Constant-Current and Primary-side Control, D0007A (SOIC-7)", Alternate Manufacturer="Texas Instruments", Alternate PartNumber=UCC28910D
U107: library part LTV-817, "Opto-Isolator, 1 Channel, TH"

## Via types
v1: diameter 20, hole 10, Top Layer to Bottom Layer, 96 vias

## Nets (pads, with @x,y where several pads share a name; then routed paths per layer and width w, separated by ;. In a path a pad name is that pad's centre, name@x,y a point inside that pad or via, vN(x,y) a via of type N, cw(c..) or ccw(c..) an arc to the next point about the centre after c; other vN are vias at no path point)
15V: C153.1 C154.1 D109.1 R140.2 R147.1 | length 472.7
  Top Layer w50: D109.1@2005.64,1227.59 2127,1227.59 C153.1@2195.74,1296.33
  Bottom Layer w50: C154.1@2195.74,1167.79 C153.1@2195.74,1296.33 ; C153.1@2195.74,1320.4 2272.58,1397.24 R147.1@2289.45,1397.24
HO: Q102.1 R110.1 U102.15 | length 804.1
  Bottom Layer w25: U102.15@3287.08,2303.93 3287.08,2346.25 3304.2,2363.37 3304.2,2548.8 3362.56,2607.15 3362.56,2999.96 Q102.1@3358.03,3004.49 3354.01,3008.5 R110.1@3289.25,3008.5
HS: C130.2 L101.1 Q101.3 Q102.3 Q103.2 R111.1 U102.16 | length 3024.5
  Top Layer w75: Q103.2@2955.43,3299.74 2955.43,3310.86 2929.55,3336.74 2929.55,3465.12 2998.22,3533.79 3261.77,3533.79 Q101.3@3395.43,3400.13 3506.5,3511.19 3506.5,3604.6 3618.22,3716.33 L101.1@4269.73,3716.33
  Bottom Layer w20: R111.1@3327.83,3337.82 R111.1@3328.5,3337.82
  Bottom Layer w25: U102.16@3337.08,2303.93 3337.08,2391.72 C130.2@3355.31,2409.95 3355.31,2551.52 3378.8,2575.01 3378.8,2576.9 3395.43,2593.54 Q102.3@3395.43,2910 3395.43,3111.19 3376.63,3130 3334.55,3130 3289.43,3175.12 3289.43,3302.95 3386.61,3400.13 Q101.3@3395.43,3400.13
ISNS: C119.1 C138.1 R129.2 U102.6 | length 621.3
  Top Layer w25: R129.2@3087.08,1990.04 3087.08,2030.58 3131.27,2074.78 3131.27,2187.51 3161.38,2217.63 v1(3182.08,2217.63) C119.1@3261.68,2217.63
  Bottom Layer w25: C138.1@3087.08,2003.16 U102.6@3087.08,2091.33 3087.08,2137.63 3167.08,2217.63 v1(3182.08,2217.63)
LO: Q104.1 R114.1 U102.10 | length 886.7
  Top Layer w25: v1(2962.08,2456.33) 3037.08,2381.33 v1(3037.08,2257.63)
  Bottom Layer w25: v1(2962.08,2456.33) 2962.08,2682.03 3013.79,2733.75 R114.1@3013.79,2938.87 ; R114.1@3020,2945.08 3038.61,2963.7 3064.06,2963.7 3082.6,2982.23 Q104.1@3082.6,3010.94 ; v1(3037.08,2257.63) U102.10@3037.08,2303.93
NetC100_2: C100.2 C106.2 C108.1 D100.3 L100.12 R105.1 R107.2 | length 3361
  Top Layer w100: L100.12@840.9,2560.85 1391.25,3111.19 D100.3@1618.73,3111.19 ; C108.1@2495.39,2977.57 C100.2@2495.39,3513.87
  Bottom Layer w50: R107.2@2378.22,2923.41 2441.22,2923.41 C108.1@2495.39,2977.57 ; C100.2@2545.2,3513.87 2574.97,3543.64 R105.1@2615.39,3543.64
  Bottom Layer w75: C106.2@236.18,3802.36 415.15,3802.36 540,3677.51 540,3150 840.9,2849.1 L100.12@840.9,2560.85
NetC101_1: C101.1 U100.3 | length 73
  Bottom Layer w25: C101.1@4140,1411.5 4157.32,1394.18 U100.3@4205.87,1394.18
NetC103_1: C103.1 U101.3 | length 78.9
  Bottom Layer w25: U101.3@5524.13,1122.6 5546.73,1100 5581.1,1100 C103.1@5590,1091.1
NetC105_2: C105.2 F100.1 J100.3 | length 838.3
  Top Layer w50: C105.2@217.39,976.04 J100.3@217.39,1192.38
  Top Layer w100: J100.3@182.11,1236.13 J100.3@221.62,1196.61
  Bottom Layer w50: C105.2@217.39,976.04 J100.3@217.39,1192.38
  Bottom Layer w100: F100.1@182.11,1530 182.11,1236.13 J100.3@221.62,1196.61
NetC107_1: C107.1 K100.2 L100.6 R108.1 RT100.2 | length 2708.7
  Bottom Layer w50: R108.1@576.28,2161.69 C107.1@684.47,2161.69
  Bottom Layer w100: L100.6@250.35,3545.1 250.35,3049.65 530,2770 530,2422.5 671.15,2281.35 K100.2@947.26,2281.35 ; 690.84,2261.66 690.84,1621.5 752.34,1560 RT100.2@911.57,1560
NetC107_2: C107.2 F100.2 L100.1 R106.2 | length 1952.5
  Top Layer w100: F100.2@182.11,1730 93.92,1818.19 C107.2@93.92,2161.69 93.92,2404.41 L100.1@250.35,2560.85
  Bottom Layer w50: C107.2@93.92,2161.69 R106.2@182.11,2161.69
  Bottom Layer w100: F100.2@182.11,1730 93.92,1818.19 C107.2@93.92,2161.69 93.92,2404.41 L100.1@250.35,2560.85
NetC110_1: C110.1 J100.1 K100.1 K100.3 RT100.1 | length 1315.7
  Top Layer w100: K100.1@947.26,1808.91 1183.48,2045.13
  Bottom Layer w50: J100.1@845.62,1196.61 922.21,1120.03 922.21,880.89 C110.1@869.72,828.4
  Bottom Layer w100: J100.1@845.62,1196.61 1108.43,1459.42 RT100.1@1108.43,1560 1108.43,1647.74
NetC111_1: C111.1 D100.2 L100.7 | length 142.5
  Bottom Layer w75: L100.7@840.9,3545.1 840.9,3687.64
NetC112_2: C112.2 C113.2 C114.2 C115.2 C116.1 C117.1 C118.1 C119.2 T100.1 | length 458.5
  Top Layer w39.37: C119.2@3375.86,2217.63 C118.1@3375.86,2327.63
  Top Layer w50: C118.1@3375.86,2327.63 3479.46,2431.23 C114.2@3681.4,2431.23
NetC114_1: C114.1 C115.1 L101.2 T100.5 | length 1044.8
  Top Layer w75: C114.1@3682.7,2823.63 C115.1@3932.7,2823.63 4281.15,2823.63 ; 4288.46,2580.01 L101.2@4288.46,3026.39
NetC128_2: C128.2 J101.3 J101.4 R116.2 R117.2 R120.2 SGND.1@4268.84,176.44 | length 2149.1
  Top Layer w25: v1(2486.88,449.28) R120.2@2486.88,492.95
  Bottom Layer w20: v1(2486.88,449.28) 2562.87,373.29 3967.59,373.29 3998.84,342.04 3998.84,291.49
  Bottom Layer w50: C128.2@3825.77,82.62 3825.77,143.37 J101.3@3858.84,176.44
  Bottom Layer w75: J101.3@3858.84,176.44 3858.84,224.74 R116.2@3925.58,291.49 3998.84,291.49 R117.2@4073.22,291.49 ; J101.4@4058.84,176.44 R117.2@4058.84,277.11
NetC130_1: C130.1 D107.1 U102.14 | length 233.7
  Bottom Layer w25: C130.1@3232.39,2392.31 C130.1@3232.39,2417.63 ; U102.14@3237.08,2303.93 D107.1@3237.08,2512.33
NetC131_1: C131.1 R120.1 U103.3 | length 140.2
  Top Layer w25: U103.3@2464.27,686.73 2464.27,640.35 C131.1@2486.91,617.71 R120.1@2486.88,555.95
NetC131_2: C131.2 R119.1 U103.4 | length 139.6
  Top Layer w25: R119.1@2551.22,555.95 2551.22,619.03 2572.54,640.35 U103.4@2572.54,686.73
NetC132_1: C132.1 D108.1 R121.1 U103.5 | length 422.9
  Top Layer w25: R121.1@2425.47,955.46 2564.3,955.46 2585.47,934.29 2585.47,774.46 U103.5@2572.54,761.54 ; C132.1@2529.09,828.3 v1(2555.47,828.3) 2578.24,828.3
  Bottom Layer w25: v1(2555.47,828.3) 2570.15,828.3 D108.1@2578.78,836.92
NetC136_1: C136.1 D111.1 R130.1 U104.1 | length 250.2
  Top Layer w25: R130.1@2642.95,1301.06 2719.8,1301.06 2733.91,1286.96 U104.1@2768.19,1286.96 2809.72,1286.96 2838.07,1315.3 D111.1@2838.07,1352.76
NetC136_2: C136.2 C137.1 C147.1 R127.1 U104.2 | length 291.9
  Top Layer w25: R127.1@2518.38,1208.15 C147.1@2614.65,1208.15 ; C147.1@2631.82,1190.98 2642.95,1202.12 C137.1@2642.95,1251.06 ; C137.1@2643.25,1251.36 C136.2@2700.63,1251.36 2715.03,1236.96 U104.2@2768.19,1236.96
NetC137_2: C137.2 R130.2 | length 50
  Top Layer w25: C137.2@2595.7,1251.06 R130.2@2595.7,1301.06
NetC139_1: C139.1 C140.1 C141.1 R118.1 R125.2 U102.12 | length 379.5
  Bottom Layer w25: R118.1@3086.72,2676.33 3086.72,2672.12 3133.57,2625.27 C141.1@3133.57,2607.63 C140.1@3133.57,2547.63 C139.1@3133.57,2487.63 R125.2@3133.57,2409.95 ; U102.12@3137.08,2303.93 R125.2@3137.08,2397.63
NetC142_1: C142.1 R125.1 R131.2 U102.9 | length 223.4
  Bottom Layer w25: R131.2@2862.08,2289.12 2972.28,2289.12 ; U102.9@2987.08,2303.93 2987.08,2377.63 R125.1@3014.99,2405.54
NetC144_1: C144.1 U102.5 U105.4 | length 410.7
  Top Layer w25: v1(3137.08,2024.51) 3137.08,2003.77 3242.08,1898.77 U105.4@3242.08,1743.46
  Bottom Layer w25: C144.1@3137.08,2005.13 v1(3137.08,2024.51) U102.5@3137.08,2091.33
NetC145_1: C145.1 R126.1 R132.2 U102.4 | length 278.1
  Top Layer w25: v1(3187.08,2024.51) R126.1@3187.08,2132.82
  Bottom Layer w25: U102.4@3187.08,2091.33 v1(3187.08,2024.51) 3187.08,2002.01 C145.1@3203.06,1986.02 ; C145.1@3203.77,1986.73 R132.2@3261.68,1986.73
NetC146_1: C146.1 R133.2 U102.8 | length 162.9
  Top Layer w25: R133.2@2962.08,1986 2983,2006.93 v1(2983,2024.51)
  Bottom Layer w25: C146.1@2962.08,1986 2983,2006.93 v1(2983,2024.51) 2983,2087.25 U102.8@2987.08,2091.33
NetC147_2: C147.2 C149.1 R134.1 R137.2 U104.3 | length 301.4
  Top Layer w25: C147.2@2698.84,1186.96 U104.3@2768.19,1186.96
  Bottom Layer w25: R134.1@2684.96,1077.88 2684.96,1135.37 v1(2735.03,1185.44) C149.1@2771.49,1185.44 ; C149.1@2780,1193.94 R137.2@2780,1261.2
NetC148_1: C148.1 R134.2 R138.2 U104.6 U104.7 | length 159
  Top Layer w50: C148.1@2684.96,1014.89 2767.92,1014.89
  Bottom Layer w25: R134.2@2684.96,1014.89 R138.2@2760.97,1014.89
  other v1: 2725.47,1015.16
NetC148_2: C148.2 C150.1 R135.1 U104.5 | length 171.6
  Top Layer w25: R135.1@2625.74,1077.88 C148.2@2684.96,1077.88 C148.2@2693.77,1086.69 ; C148.2@2703.61,1086.96 v1(2725.47,1086.96) U104.5@2768.19,1086.96
  Bottom Layer w25: v1(2725.47,1086.96) C150.1@2760.86,1086.96
NetC155_1: C155.1 D111.2 R143.1 U104.14 | length 265.1
  Top Layer w25: D111.2@2912.87,1352.76 2912.87,1319.83 2945.74,1286.96 U104.14@2982.75,1286.96 2998.56,1286.96 3017.64,1306.04 3017.64,1315.17 3042.21,1339.74 R143.1@3104.25,1339.74
NetC155_2: C155.2 C156.1 C159.1 R145.1 R156.2 U104.13 | length 323.2
  Top Layer w25: U104.13@2984.02,1238.23 v1(3015.47,1238.23) C159.1@3049.83,1238.23 C155.2@3049.83,1290.98 ; C155.2@3051.34,1292.49 C156.1@3104.25,1292.49
  Bottom Layer w25: v1(3015.47,1238.23) R145.1@3098.5,1238.23 ; R156.2@3103.26,1164.74 R145.1@3103.26,1233.46
NetC156_2: C156.2 R143.2 | length 47.2
  Top Layer w20: C156.2@3151.49,1292.49 R143.2@3151.49,1339.74
NetC157_1: C157.1 C158.1 C163.1 C164.2 D113.1 Q106.2 R148.2 U106.6 | length 784.8
  Top Layer w25: v1(2213.98,2026.33) C164.2@2213.98,2057.32 ; v1(2696.23,1976.33) C157.1@2696.23,2007.95
  Top Layer w39.37: D113.1@2330.93,2076.27 C163.1@2480.52,2076.27 2544.17,2076.27 2590.84,2122.95 2658.44,2122.95 2690.33,2091.06 C157.1@2690.33,2013.85
  Bottom Layer w20: C158.1@2337.47,2061.04 2352.75,2076.33 v1(2366.02,2076.33)
  Bottom Layer w25: U106.6@2213.98,1980.83 v1(2213.98,2026.33) 2248.69,2061.04 C158.1@2337.47,2061.04 ; v1(2696.23,1976.33) Q106.2@2696.23,2011.1
NetC157_2: C157.2 Q106.1 R148.1 U107.4 | length 372.7
  Top Layer w29.53: v1(2590.52,1980.18) 2627.34,2017 R148.1@2627.34,2076.69
  Bottom Layer w39.37: U107.4@2510.52,1832.28 2589.93,1911.69 2589.93,1979.6 v1(2590.52,1980.18) Q106.1@2621.43,2011.1 2621.43,2047.23
NetC159_2: C159.2 C161.1 R151.2 R155.2 U104.12 | length 272.4
  Top Layer w25: U104.12@2982.75,1186.96 3077.49,1186.96 3077.49,1188.55 3083.28,1188.55 C161.1@3106.22,1211.48 R151.2@3165.47,1211.48 ; R151.2@3169.76,1211.48 R155.2@3248.38,1211.48
NetC160_1: C160.1 R151.1 R157.2 U104.8 U104.9 | length 692.8
  Top Layer w20: U104.8@2982.75,986.96 U104.9@2982.75,1036.96 3038.08,1036.96 C160.1@3055.47,1019.57 3055.47,924.65 3081.12,899 3178.41,899 3195.47,916.06 v1(3195.47,971.06) R157.2@3195.47,1019.57 ; R151.1@3172.89,1141.06 v1(3205.47,1141.06)
  Bottom Layer w20: v1(3195.47,971.06) 3205.47,981.06 v1(3205.47,1141.06)
NetC160_2: C160.2 C162.1 R152.1 U104.10 | length 238.4
  Top Layer w20: C160.2@3055.47,1082.56 3056.14,1082.56 3092.04,1046.66 3092.04,1045.98 3118.46,1019.57 C162.1@3124.92,1019.57 R152.1@3124.92,945.42
  Top Layer w25: U104.10@2982.75,1086.96 C160.2@3051.07,1086.96
NetCCset_1: CCset.1 R135.2 R139.2 | length 933
  Top Layer w39.37: CCset.1@2606.16,177.28 2606.16,386.16 2625.47,405.47 2625.47,757.75 2625.53,757.81 2625.53,1015.1 R135.2@2625.47,1015.16
  Bottom Layer w39.37: CCset.1@2598.66,158.39 2643.25,113.8 R139.2@2643.25,89.78
NetCVset_1: CVset.1 R152.2 R158.2 | length 853.6
  Top Layer w39.37: CVset.1@2897.35,169.78 2897.35,309.17 2988.97,400.79 2988.97,689.4 R152.2@3127.87,828.3
  Bottom Layer w39.37: CVset.1@2897.35,169.78 2945.16,121.97 R158.2@2945.16,90
NetD101_1: D101.1 Q101.1 Q102.2 R111.2 | length 305
  Bottom Layer w29.53: R111.2@3328.5,3274.83 Q101.1@3395.43,3207.9 ; Q101.1@3395.43,3199.34 3432.83,3161.94 Q102.2@3432.83,3004.49
NetD101_2: D101.2 R110.2 | length 55.8
  Bottom Layer w25: R110.2@3289.25,3071.5 D101.2@3345.04,3071.5
NetD103_2: D103.2 D104.2 | length 159
  Bottom Layer w50: D103.2@1095.53,2146.33 1095.53,2007.78 D104.2@1110,1993.31
NetD104_1: D104.1 K100.4 R112.1 R113.1 | length 360.7
  Bottom Layer w50: D104.1@1110,1906.69 1220.46,1906.69 R112.1@1223.62,1909.86 1326.62,1909.86 K100.4@1427.57,1808.91
NetD105_1: D105.1 Q103.1 Q104.2 R115.2 | length 463.4
  Bottom Layer w25: R115.2@3122.36,3327.82 3129.41,3327.82 3162.42,3294.81 3162.42,3229.93 3122.36,3189.87 3122.36,3093.04 3157.4,3058 Q104.2@3157.4,3010.94
  Bottom Layer w39.37: Q103.1@3055.43,3394.75 R115.2@3122.36,3327.82
NetD105_2: D105.2 R114.2 | length 78.8
  Bottom Layer w25: R114.2@3020,3008.07 3036.69,3024.77 D105.2@3036.69,3080
NetD107_2: D107.2 R118.2 | length 90.7
  Bottom Layer w39.37: R118.2@3149.72,2676.33 D107.2@3240.44,2676.33
NetD109_2: D109.2 T101.5 T101.6 | length 327.1
  Top Layer w75: D109.2@2005.64,1385.07 2005.64,1488.69 T101.5@2025.06,1508.11 T101.6@2123.06,1508.11
  Bottom Layer w75: T101.5@2025.06,1508.11 T101.6@2123.06,1508.11
NetD110_1: D110.1 D112.1
  other v1: 1644.56,1881.17 1671.67,1881.17 1700,1881.17
NetD111_3: D111.3 U105.2 | length 515
  Top Layer w25: D111.3@2875.47,1447.24 2932.16,1447.24 2992.52,1386.88 3285.5,1386.88 U105.2@3342.08,1443.46
NetD112_2: D112.2 T101.3 U106.8 | length 379.8
  Top Layer w50: D112.2@1867.84,1812.28 1960.51,1719.61 2077.55,1719.61 2133.56,1775.62 T101.3@2133.56,1828.11
NetD113_2: D113.2 R144.1 | length 45.6
  Top Layer w39.37: R144.1@2337.47,1936.65 D113.2@2337.47,1982.3
NetPSON_1: PSON.1 R154.2 | length 1207.3
  Top Layer w39.37: PSON.1@2100,169.78 2250,319.78 2250,1019.22 v1(2406.77,1175.99)
  Bottom Layer w39.37: v1@2414.43,1175.87 R154.2@2488.5,1175.87
NetQ107_1: Q107.1 R154.1 R159.2 | length 115.9
  Bottom Layer w25: R159.2@2559.54,1249.52 Q107.1@2559.54,1302.76
  Bottom Layer w39.37: R154.1@2551.5,1175.87 R159.2@2551.5,1238.52
NetQ107_3: Q107.3 R150.1 U107.2 | length 171.6
  Bottom Layer w39.37: Q107.3@2522.14,1397.24 2553.62,1428.72 R150.1@2553.62,1461.96 2581.86,1490.2 2581.86,1503.62 U107.2@2610.52,1532.28
NetR100_2: R100.2 U100.5 | length 86.4
  Bottom Layer w50: R100.2@4317.09,1230 U100.5@4317.09,1316.42
NetR101_2: R101.2 U101.5 | length 85.5
  Bottom Layer w50: U101.5@5415.87,1197.4 5415.87,1272.95 R101.2@5422.91,1280
NetR102_1: R102.1 R105.2 | length 85.8
  Bottom Layer w50: R105.2@2615.39,3657.81 R102.1@2615.39,3743.64
NetR103_2: R103.2 U100.1 | length 228.6
  Bottom Layer w25: U100.1@4205.87,1319.38 4220.62,1319.38 4260,1280 4260,1187.44 R103.2@4213.62,1141.06
NetR104_2: R104.2 U101.1 | length 228.2
  Bottom Layer w29.53: U101.1@5524.13,1197.4 5509.53,1197.4 5480,1226.93 5480,1330 5510,1360 R104.2@5536.38,1360
NetR106_1: R106.1 R108.2 | length 165.8
  Bottom Layer w50: R106.1@296.28,2161.69 R108.2@462.11,2161.69
NetR107_1: R107.1 R109.2 | length 85.8
  Bottom Layer w50: R109.2@2378.22,2723.41 R107.1@2378.22,2809.24
NetR122_1: R122.1 U102.1 | length 55.6
  Bottom Layer w25: U102.1@3341.15,2087.25 R122.1@3396.72,2087.25
NetR123_1: R123.1 R124.2 | length 282.3
  Top Layer w39.37: R123.1@2859.89,1860.91 2859.89,2141.42 R124.2@2861.13,2142.66
NetR124_1: R124.1 R126.2 | length 87.8
  Top Layer w39.37: R124.1@2975.31,2142.66 R126.2@3063.06,2142.66
NetR127_2: R127.2 R128.1 | length 82.9
  Top Layer w25: R128.1@2518.38,1011.06 R127.2@2518.38,1093.98
NetR128_2: R128.2 U103.1 | length 196.7
  Top Layer w25: U103.1@2464.27,761.54 2445.47,780.34 2445.47,851.06 2492.19,897.78 R128.2@2525.47,897.78
NetR136_1: R136.1 U105.1 | length 92.8
  Bottom Layer w50: U105.1@3242.08,1443.46 3242.08,1357.76 R136.1@3247.08,1352.76
NetR141_2: R141.2 U105.3 | length 74.3
  Bottom Layer w39.37: U105.3@3342.08,1743.46 R141.2@3342.08,1817.76
NetR142_1: R142.1 R145.2 | length 79.9
  Bottom Layer w25: R145.2@3164.98,1234.74 R142.1@3244.89,1234.74
NetR144_2: R144.2 R146.2 T101.2 | length 246.9
  Top Layer w39.37: T101.2@2221.06,1828.11 2221.06,1883.23 R144.2@2274.48,1936.65
  Bottom Layer w39.37: T101.2@2221.06,1828.11 2221.06,1878.69 2250.48,1908.11 R146.2@2274.48,1908.11
NetR146_1: R146.1 R153.2 U106.5 | length 144.6
  Bottom Layer w25: U106.5@2263.98,1980.83 2334.76,1980.83 R153.2@2336.48,1979.11 2337.47,1978.11 R146.1@2337.47,1908.11
NetR147_2: R147.2 R150.2 U107.1 | length 192.4
  Bottom Layer w39.37: R147.2@2403.62,1397.24 2468.33,1461.96 R150.2@2490.62,1461.96 2490.62,1512.38 U107.1@2510.52,1532.28
NetR149_2: R149.2 U106.4 | length 70.5
  Bottom Layer w29.53: U106.4@2263.98,2195.39 R149.2@2263.98,2265.85
PE: C105.1 C106.1 C110.2 C111.2 J100.2 | length 3935.8
  Top Layer w50: C106.1@383.82,4097.64 490,4097.64 C111.2@873.82,4097.64 ; C105.1@512.67,828.4 574.44,890.18 C110.2@574.44,976.04 533.62,1016.86 J100.2@533.62,1196.61
  Top Layer w75: 490,4097.64 490,3685.76 540,3635.76 540,2440 400,2300 400,1450 533.62,1316.38 J100.2@533.62,1196.61
PGND: C108.2 C109.2 C116.2 C117.2 C129.1 C134.1 C135.1 C138.2 C139.2 C140.2 C141.2 C142.2 C143.2 C144.2 C145.2 C146.2 C151.2 C152.2 C158.2 C163.2 C164.1 D100.4 D103.1 H100.1 H100.2 H102.1 H102.2 K100.5 Q103.3 Q104.3 R109.1 R115.1 R122.2 R129.1 R131.1 R132.1 R133.1 R141.1 R149.1 R153.1 T101.1 U102.11 U106.1 U106.2 U106.3 U107.3 | length 9702.5
  Top Layer w25: C163.2@2480.52,1997.53 2610.52,1867.53 U107.3@2610.52,1832.28 ; v1(2912.08,2057.63) 3012.08,2057.63 3032.08,2037.63 3032.08,1960.07 3069.12,1923.03 R129.1@3083.06,1923.03
  Top Layer w29.53: v1(2210.52,2153.3) 2210.52,2134.35 2310.92,2033.95 2443.58,2033.95 2480,1997.53 C163.2@2480.52,1997.53
  Top Layer w50: 2346.53,1828.11 2438.22,1919.8 2438.22,1955.23 C163.2@2480.52,1997.53
  Top Layer w75: C108.2@2495.39,2583.87 2658.22,2746.71 2658.22,2802.13 Q103.3@3055.43,3199.34 3185.38,3069.4 3609.97,3069.4 C116.2@3682.48,2996.89 C117.2@3932.48,2996.89
  Top Layer w100: H100.1@1498.22,3711.19 2673.35,3711.19
  Bottom Layer w25: 1422.18,2190 1395.64,2163.46 1395.64,2017.97 1408.38,2005.24 1408.38,2004.56 1422.87,1990.07 1422.87,1939.94 1550,1812.82 1550,1760 1620,1690 1800.96,1690 1840.96,1730 2290.02,1730 2319.06,1759.04 T101.1@2319.06,1828.11 ; R131.1@2862.08,2226.13 2970.74,2226.13 2989.24,2207.63 ; C141.2@3070.58,2607.63 3046.66,2631.54 3046.66,2843.12 Q104.3@3120,2916.45 3120,3030.87 3074.44,3076.44 Q103.3@3074.44,3180.34 ; C141.2@3072.08,2597.65 3072.08,2357.63 3083.2,2346.51 3083.2,2307.8 U102.11@3087.08,2303.93 3087.08,2262.63 v1(3072.08,2247.63) 3072.08,2241.23 3038.48,2207.63 2989.24,2207.63 ; v1(3143.06,1874.51) C144.2@3143.06,1923.03 C146.2@2962.08,1923.01 2953.57,1923.01 2912.08,1964.51 2912.08,2130.46 2989.24,2207.63 ; C144.2@3143.06,1923.03 C145.2@3203.06,1923.03 3308.98,1923.03
  Bottom Layer w39.37: Q103.3@3055.43,3199.34 3120.92,3264.83 R115.1@3122.36,3264.83 ; R141.1@3222.2,1823.46 3222.2,1903.89 ; C134.1@3328.22,1924.83 C135.1@3388.22,1924.83 3416.72,1924.83 3459.72,1967.82 R122.2@3459.72,2087.25
  Bottom Layer w50: D103.1@1224.47,2146.33 1269.02,2190.88 C129.1@1320,2190.88 1385.44,2190.88 1386.32,2190 1422.18,2190 1422.18,2275.95 K100.5@1427.57,2281.35 ; T101.1@2319.06,1828.11 2346.53,1828.11 2399.47,1881.05 R153.1@2399.47,1979.11 2462.1,1979.11 C163.2@2480.52,1997.53 ; C108.2@2495.39,2583.87 2618.22,2461.04 2618.22,2396.33 2788.41,2226.13 R131.1@2862.08,2226.13
  Bottom Layer w75: 3808.22,2980.18 3808.22,2359.77 C109.2@3858.84,2310
  other v1: 2962.08,1773.87 2996.52,1874.51 3438.22,1946.33 2912.08,1966.33 3459.72,2006.33 2746.59,2114.94 2798.22,2116.33 2468.22,2226.33 2168.22,2246.33 2528.22,2246.33 2078.22,2247.63 2123.06,2247.63 2468.22,2266.33 1948.22,2305.08 2468.22,2305.5 1948.22,2336.33 1978.22,2366.33 3028.22,2476.33 3028.22,2536.33 3028.22,2593.54 2898.22,2656.33 2918.22,2726.33
Relay: C129.2 J102.1 Q106.3 R112.2 R113.2 | length 2115.6
  Bottom Layer w25: R113.2@1330,2024.03 1343.09,2024.03 1375.51,1991.62 1375.51,1990.95 1390,1976.45 1390,1926.33 1517.13,1799.2 1517.13,1742.87 1602.87,1657.13 1814.57,1657.13 1854.57,1697.13 2382.16,1697.13 2450,1764.96 2617.87,1764.96 2658.83,1805.93 Q106.3@2658.83,1916.61
  Bottom Layer w50: R112.2@1223.62,2024.03 R113.2@1330,2024.03 ; R113.2@1320,2034.03 C129.2@1320,2110.88 ; Q106.3@2658.83,1916.61 2724.85,1916.61 2760.52,1952.28 J102.1@2760.52,2052.28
